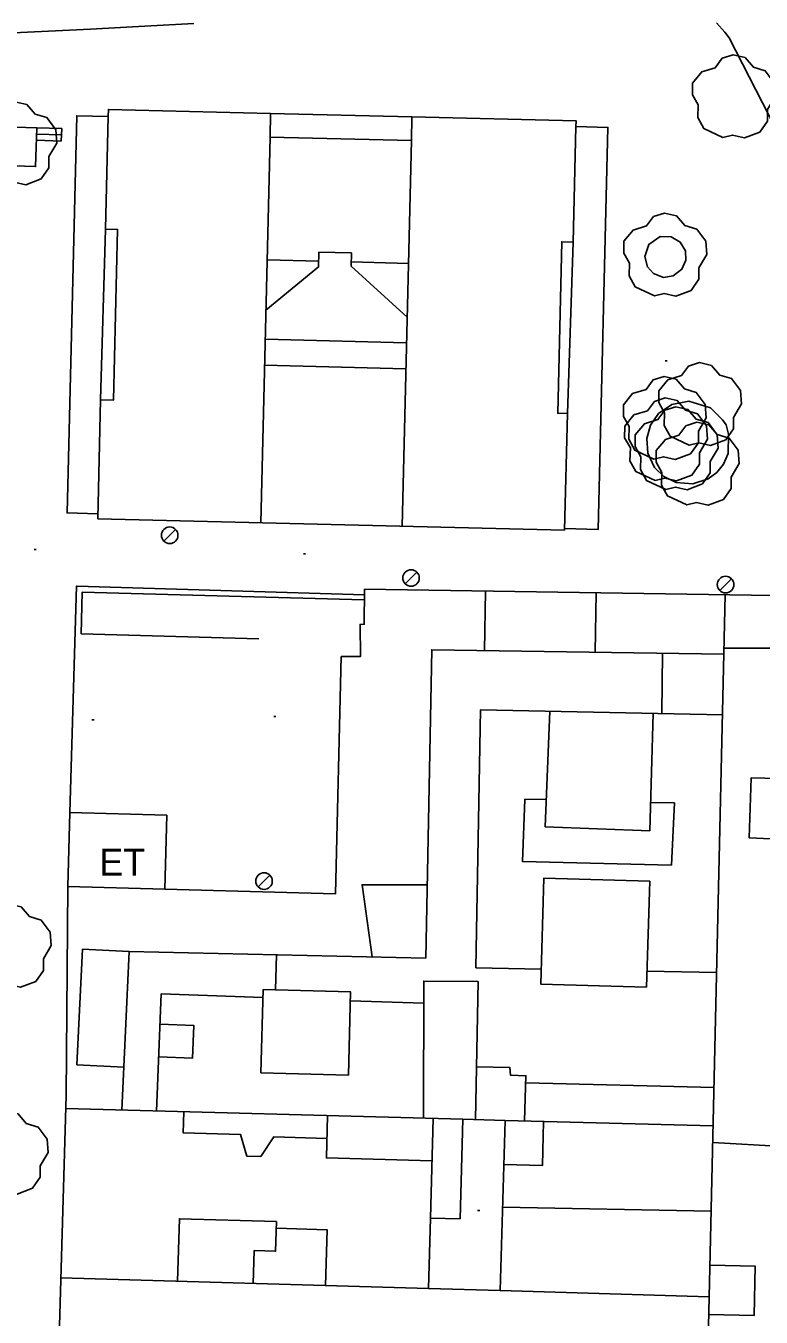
# Model space of a CAD drawing. Extents: x 431390 to 432653, y 4586754 to 4589600.
# Drawn here: x 431486.3 to 431521.7, y 4587036.9 to 4587099.1 of the extents above; entities that cross this region are included whole.
import ezdxf

# ---------------------------------------------------------------- set-up
doc = ezdxf.new("R2010")
doc.units = 0
for name, color, linetype in [('COM_17LS_LN', 7, 'Continuous'), ('CON_01_LN', 7, 'Continuous'), ('CON_01FI_LN', 7, 'Continuous'), ('CON_03_LN', 7, 'Continuous'), ('CON_04_LN', 7, 'Continuous'), ('CON_08_LN', 7, 'Continuous'), ('CON_14LS_LN', 7, 'Continuous'), ('CON_15_LN', 7, 'Continuous'), ('CON_16_LN', 7, 'Continuous'), ('CON_20_LN', 7, 'Continuous'), ('CON_23_LN', 7, 'Continuous'), ('ENE_06_PT', 7, 'Continuous'), ('ORO_03_PT', 7, 'Continuous'), ('TOP_14_TX', 7, 'Continuous'), ('VEG_03_PT', 7, 'Continuous')]:
    doc.layers.add(name, color=color, linetype=linetype)

msp = doc.modelspace()

# ---------------------------------------------------------------- linework, layer by layer
at = {"layer": 'COM_17LS_LN'}
for points in [[(431454.052, 4587099.254), (431458.563, 4587098.932), (431463.027, 4587098.704), (431467.449, 4587098.555), (431471.887, 4587098.473), (431476.364, 4587098.469), (431480.875, 4587098.554), (431485.348, 4587098.739), (431487.372, 4587098.835), (431489.397, 4587098.931), (431491.42, 4587099.04), (431494.389, 4587099.203)], [(431519.591, 4587099.231), (431519.988, 4587098.79), (431520.198, 4587098.522), (431524.709, 4587089.743), (431525.226, 4587088.745)]]:
    msp.add_lwpolyline(points, dxfattribs=at)
at = {"layer": 'CON_01_LN'}
for points in [[(431498.088, 4587094.874), (431490.265, 4587095.063), (431490.257, 4587094.724)], [(431512.813, 4587094.233), (431512.82, 4587094.517), (431504.902, 4587094.709)], [(431488.313, 4587057.601), (431488.231, 4587047.535)], [(431486.921, 4587002.7), (431487.096, 4587008.671), (431487.106, 4587009.016), (431487.323, 4587016.451), (431488.231, 4587047.535)]]:
    msp.add_lwpolyline(points, dxfattribs=at)
at = {"layer": 'CON_01FI_LN'}
for points in [[(431490.257, 4587094.724), (431490.126, 4587089.296)], [(431498.06, 4587093.724), (431498.088, 4587094.874)], [(431504.902, 4587094.709), (431504.874, 4587093.559)], [(431512.679, 4587088.669), (431512.813, 4587094.233)], [(431504.874, 4587093.559), (431498.06, 4587093.724)], [(431490.126, 4587089.296), (431489.887, 4587081.058)], [(431512.679, 4587088.669), (431512.398, 4587080.406)], [(431489.887, 4587081.058), (431489.749, 4587075.335)], [(431512.262, 4587074.789), (431512.398, 4587080.406)], [(431489.749, 4587075.334), (431512.262, 4587074.789)], [(431502.608, 4587071.939), (431502.6, 4587070.25), (431502.4, 4587070.24), (431502.42, 4587068.69), (431501.49, 4587068.69), (431501.22, 4587057.26), (431492.983, 4587057.477)], [(431502.608, 4587071.939), (431522.313, 4587071.636)], [(431488.406, 4587061.169), (431488.313, 4587057.601)], [(431492.983, 4587057.477), (431493.076, 4587061.047), (431488.406, 4587061.169)], [(431509.163, 4587038.133), (431505.703, 4587038.234), (431505.794, 4587041.629), (431507.223, 4587041.591), (431507.352, 4587046.392)], [(431507.352, 4587046.392), (431509.403, 4587046.338)], [(431509.403, 4587046.338), (431509.163, 4587038.133)]]:
    msp.add_lwpolyline(points, dxfattribs=at)
at = {"layer": 'CON_03_LN'}
for points in [[(431518.933, 4587021.903), (431518.973, 4587025.83), (431520.009, 4587071.671)], [(431492.983, 4587057.477), (431488.313, 4587057.601)], [(431488.213, 4587046.905), (431507.352, 4587046.392)], [(431509.403, 4587046.338), (431519.43, 4587046.069)], [(431487.974, 4587038.752), (431505.703, 4587038.234)], [(431509.163, 4587038.133), (431519.244, 4587037.838)]]:
    msp.add_lwpolyline(points, dxfattribs=at)
at = {"layer": 'CON_04_LN'}
for points in [[(431497.61, 4587075.144), (431498.06, 4587093.724)], [(431504.874, 4587093.559), (431504.424, 4587074.979)], [(431490.126, 4587089.296), (431490.703, 4587089.282), (431490.504, 4587081.043), (431489.887, 4587081.058)], [(431512.398, 4587080.406), (431511.932, 4587080.417), (431512.132, 4587088.682), (431512.679, 4587088.669)], [(431497.858, 4587085.389), (431500.401, 4587087.47), (431500.418, 4587088.188), (431501.987, 4587088.15), (431501.972, 4587087.509), (431504.668, 4587085.043)], [(431500.408, 4587087.748), (431497.917, 4587087.808)], [(431504.731, 4587087.643), (431501.977, 4587087.71)], [(431504.638, 4587083.817), (431497.824, 4587083.982)], [(431504.608, 4587082.564), (431497.794, 4587082.729)], [(431508.407, 4587068.981), (431508.451, 4587071.849)], [(431513.782, 4587071.767), (431513.738, 4587068.9)], [(431490.904, 4587046.833), (431491.26, 4587054.48), (431505.57, 4587054.16), (431505.86, 4587069.02), (431519.944, 4587068.805)], [(431547.7, 4587024.987), (431548.13, 4587035.11), (431527.57, 4587069.09), (431519.951, 4587069.092)], [(431516.958, 4587065.942), (431516.99, 4587068.85)], [(431519.878, 4587065.879), (431508.21, 4587066.13), (431507.99, 4587053.69), (431511.141, 4587053.63)], [(431516.541, 4587065.951), (431516.37, 4587060.3), (431511.33, 4587060.48), (431511.555, 4587066.058)], [(431523.93, 4587058.46), (431528.17, 4587058.26), (431528.31, 4587061.41), (431527.12, 4587061.42), (431527.13, 4587062.7), (431521.26, 4587062.84), (431521.17, 4587059.95), (431523.95, 4587059.83), (431523.93, 4587058.46)], [(431516.411, 4587061.66), (431517.56, 4587061.64), (431517.42, 4587058.64), (431510.23, 4587058.82), (431510.34, 4587061.81), (431511.384, 4587061.817)], [(431516.217, 4587052.751), (431516.37, 4587057.86), (431511.271, 4587058.012), (431511.119, 4587052.903), (431516.217, 4587052.751)], [(431505.639, 4587057.686), (431502.5, 4587057.69), (431502.987, 4587054.218)], [(431491, 4587048.901), (431488.747, 4587049.006), (431489.007, 4587054.585), (431491.26, 4587054.48)], [(431498.326, 4587052.628), (431498.371, 4587054.321)], [(431516.24, 4587053.533), (431519.598, 4587053.469)], [(431507.971, 4587046.376), (431508.09, 4587053.03), (431505.47, 4587053.05), (431505.457, 4587046.443)], [(431497.711, 4587052.256), (431492.81, 4587052.43), (431492.589, 4587046.788)], [(431501.84, 4587048.516), (431501.947, 4587052.531), (431497.721, 4587052.644), (431497.613, 4587048.629), (431501.84, 4587048.516)], [(431505.468, 4587051.98), (431501.936, 4587052.106)], [(431492.692, 4587049.406), (431494.32, 4587049.342), (431494.381, 4587050.911), (431492.753, 4587050.975)], [(431510.324, 4587046.313), (431510.4, 4587048.49), (431509.65, 4587048.52), (431509.63, 4587048.88), (431508.016, 4587048.911)], [(431519.472, 4587047.927), (431510.388, 4587048.14)], [(431493.901, 4587046.753), (431493.874, 4587045.729), (431496.634, 4587045.655), (431496.938, 4587044.618), (431497.611, 4587044.6), (431498.24, 4587045.538), (431500.805, 4587045.469)], [(431500.835, 4587046.567), (431500.78, 4587044.53), (431505.868, 4587044.394)], [(431505.923, 4587046.43), (431505.794, 4587041.629)], [(431511.25, 4587046.288), (431511.193, 4587044.155), (431509.341, 4587044.204)], [(431529.732, 4587019.557), (431529.93, 4587027.07), (431527.73, 4587027.05), (431528.01, 4587032.73), (431526.54, 4587032.61), (431526.05, 4587036.78), (431523.42, 4587036.76), (431523.55, 4587041.44), (431522.67, 4587041.42), (431522.77, 4587045.08), (431519.412, 4587045.274)], [(431519.337, 4587041.957), (431509.281, 4587042.158)], [(431493.597, 4587038.588), (431493.685, 4587041.595), (431498.366, 4587041.458), (431498.324, 4587040.03), (431497.292, 4587040.06), (431497.246, 4587038.481)], [(431500.732, 4587038.379), (431500.811, 4587041.066), (431498.357, 4587041.138)], [(431519.225, 4587036.98), (431521.401, 4587036.931), (431521.455, 4587039.314), (431519.279, 4587039.363)]]:
    msp.add_lwpolyline(points, dxfattribs=at)
at = {"layer": 'CON_08_LN'}
for points in [[(431490.257, 4587094.724), (431488.735, 4587094.76), (431488.267, 4587075.612), (431489.755, 4587075.575)], [(431504.902, 4587094.709), (431498.088, 4587094.874)], [(431512.813, 4587094.233), (431514.355, 4587094.197), (431513.89, 4587074.824), (431512.264, 4587074.864)]]:
    msp.add_lwpolyline(points, dxfattribs=at)
at = {"layer": 'CON_14LS_LN'}
for points in [[(431481.993, 4587094.326), (431486.811, 4587094.175), (431486.752, 4587092.305), (431481.934, 4587092.457), (431481.993, 4587094.326)], [(431502.606, 4587071.42), (431489.003, 4587071.803), (431488.946, 4587069.795), (431497.519, 4587069.553)]]:
    msp.add_lwpolyline(points, dxfattribs=at)
at = {"layer": 'CON_15_LN'}
for points in [[(431488.01, 4587094.138), (431487.991, 4587093.538)], [(431516.132, 4587087.971), (431516.322, 4587088.554), (431516.873, 4587088.931), (431517.407, 4587088.926), (431517.844, 4587088.666), (431518.09, 4587088.246), (431518.116, 4587087.799), (431517.927, 4587087.36), (431517.508, 4587087.039), (431517.029, 4587086.97), (431516.55, 4587087.151), (431516.258, 4587087.476), (431516.132, 4587087.971)], [(431518.26, 4587081.009), (431517.436, 4587080.842), (431516.788, 4587080.4), (431516.406, 4587079.85), (431516.227, 4587079.206), (431516.28, 4587078.497), (431516.608, 4587077.81), (431517.055, 4587077.372), (431517.648, 4587077.082), (431518.449, 4587077.014), (431519.186, 4587077.251), (431519.614, 4587077.57), (431519.926, 4587077.963), (431520.148, 4587078.484), (431520.175, 4587079.405), (431520.06, 4587079.868), (431519.881, 4587080.108), (431519.306, 4587080.677), (431518.26, 4587081.009)]]:
    msp.add_lwpolyline(points, dxfattribs=at)
at = {"layer": 'CON_16_LN'}
msp.add_lwpolyline([(431488.406, 4587061.169), (431488.73, 4587072.09), (431488.75, 4587072.09)], dxfattribs=at)
at = {"layer": 'CON_20_LN'}
msp.add_lwpolyline([(431488.75, 4587072.09), (431502.607, 4587071.67)], dxfattribs=at)
at = {"layer": 'CON_23_LN'}
for points in [[(431486.811, 4587094.175), (431488.01, 4587094.138)], [(431486.792, 4587093.575), (431487.991, 4587093.538)], [(431486.802, 4587093.875), (431488, 4587093.838)]]:
    msp.add_lwpolyline(points, dxfattribs=at)
at = {"layer": 'ENE_06_PT'}
for p, q in [((431493.502, 4587074.822), (431492.936, 4587074.256)), ((431505.142, 4587072.762), (431504.576, 4587072.196)), ((431520.312, 4587072.444), (431519.746, 4587071.878)), ((431498.052, 4587058.152), (431497.486, 4587057.586))]:
    msp.add_line(p, q, dxfattribs=at)
for centre in [(431493.219, 4587074.539), (431504.859, 4587072.479), (431520.029, 4587072.161), (431497.769, 4587057.869)]:
    msp.add_circle(centre, 0.4, dxfattribs=at)
at = {"layer": 'ORO_03_PT'}
for p, q in [((431517.12, 4587082.95), (431517.22, 4587082.95)), ((431486.68, 4587073.85), (431486.78, 4587073.85)), ((431499.67, 4587073.64), (431499.77, 4587073.64)), ((431489.47, 4587065.64), (431489.57, 4587065.64)), ((431498.24, 4587065.81), (431498.34, 4587065.81)), ((431508.07, 4587041.99), (431508.17, 4587041.99))]:
    msp.add_line(p, q, dxfattribs=at)
at = {"layer": 'VEG_03_PT'}
for points in [[(431519.904, 4587093.711), (431518.977, 4587094.146), (431518.689, 4587094.667), (431518.712, 4587095.281), (431518.43, 4587095.773), (431518.438, 4587096.336), (431518.879, 4587096.871), (431519.532, 4587097.075), (431519.867, 4587097.526), (431520.393, 4587097.696), (431520.973, 4587097.563), (431521.373, 4587097.097), (431521.947, 4587096.927), (431522.381, 4587096.344), (431522.43, 4587095.702), (431522.047, 4587095.055), (431522.047, 4587094.505), (431521.675, 4587093.971), (431520.936, 4587093.696), (431520.371, 4587093.824), (431519.904, 4587093.711)], [(431485.254, 4587091.451), (431484.327, 4587091.886), (431484.039, 4587092.407), (431484.062, 4587093.021), (431483.78, 4587093.513), (431483.788, 4587094.076), (431484.229, 4587094.611), (431484.882, 4587094.815), (431485.217, 4587095.266), (431485.743, 4587095.436), (431486.323, 4587095.303), (431486.723, 4587094.837), (431487.297, 4587094.667), (431487.731, 4587094.084), (431487.78, 4587093.442), (431487.397, 4587092.795), (431487.397, 4587092.245), (431487.025, 4587091.711), (431486.286, 4587091.436), (431485.721, 4587091.564), (431485.254, 4587091.451)], [(431516.594, 4587086.081), (431515.667, 4587086.516), (431515.379, 4587087.037), (431515.402, 4587087.651), (431515.12, 4587088.143), (431515.128, 4587088.706), (431515.569, 4587089.241), (431516.222, 4587089.445), (431516.557, 4587089.896), (431517.083, 4587090.066), (431517.663, 4587089.933), (431518.063, 4587089.467), (431518.637, 4587089.297), (431519.071, 4587088.714), (431519.12, 4587088.072), (431518.737, 4587087.425), (431518.737, 4587086.875), (431518.365, 4587086.341), (431517.626, 4587086.066), (431517.061, 4587086.194), (431516.594, 4587086.081)], [(431518.277, 4587078.875), (431517.35, 4587079.31), (431517.062, 4587079.831), (431517.085, 4587080.445), (431516.803, 4587080.937), (431516.811, 4587081.5), (431517.252, 4587082.035), (431517.905, 4587082.239), (431518.24, 4587082.69), (431518.766, 4587082.86), (431519.346, 4587082.727), (431519.746, 4587082.261), (431520.32, 4587082.091), (431520.754, 4587081.508), (431520.803, 4587080.866), (431520.42, 4587080.219), (431520.42, 4587079.669), (431520.048, 4587079.135), (431519.309, 4587078.86), (431518.744, 4587078.988), (431518.277, 4587078.875)], [(431516.573, 4587078.207), (431515.646, 4587078.642), (431515.358, 4587079.163), (431515.381, 4587079.777), (431515.099, 4587080.269), (431515.107, 4587080.832), (431515.548, 4587081.367), (431516.201, 4587081.571), (431516.536, 4587082.022), (431517.062, 4587082.192), (431517.642, 4587082.059), (431518.042, 4587081.593), (431518.616, 4587081.423), (431519.05, 4587080.84), (431519.099, 4587080.198), (431518.716, 4587079.551), (431518.716, 4587079.001), (431518.344, 4587078.467), (431517.605, 4587078.192), (431517.04, 4587078.32), (431516.573, 4587078.207)], [(431516.634, 4587077.175), (431515.707, 4587077.61), (431515.419, 4587078.131), (431515.442, 4587078.745), (431515.16, 4587079.237), (431515.168, 4587079.8), (431515.609, 4587080.335), (431516.262, 4587080.539), (431516.597, 4587080.99), (431517.123, 4587081.16), (431517.703, 4587081.027), (431518.103, 4587080.561), (431518.677, 4587080.391), (431519.111, 4587079.808), (431519.16, 4587079.166), (431518.777, 4587078.519), (431518.777, 4587077.969), (431518.405, 4587077.435), (431517.666, 4587077.16), (431517.101, 4587077.288), (431516.634, 4587077.175)], [(431517.141, 4587076.75), (431516.214, 4587077.185), (431515.926, 4587077.706), (431515.949, 4587078.32), (431515.667, 4587078.812), (431515.675, 4587079.375), (431516.116, 4587079.91), (431516.769, 4587080.114), (431517.104, 4587080.565), (431517.63, 4587080.735), (431518.21, 4587080.602), (431518.61, 4587080.136), (431519.184, 4587079.966), (431519.618, 4587079.383), (431519.667, 4587078.741), (431519.284, 4587078.094), (431519.284, 4587077.544), (431518.912, 4587077.01), (431518.173, 4587076.735), (431517.608, 4587076.863), (431517.141, 4587076.75)], [(431518.155, 4587076.001), (431517.228, 4587076.436), (431516.94, 4587076.957), (431516.963, 4587077.571), (431516.681, 4587078.063), (431516.689, 4587078.626), (431517.13, 4587079.161), (431517.783, 4587079.365), (431518.118, 4587079.816), (431518.644, 4587079.986), (431519.224, 4587079.853), (431519.624, 4587079.387), (431520.198, 4587079.217), (431520.632, 4587078.634), (431520.681, 4587077.992), (431520.298, 4587077.345), (431520.298, 4587076.795), (431519.926, 4587076.261), (431519.187, 4587075.986), (431518.622, 4587076.114), (431518.155, 4587076.001)], [(431484.984, 4587052.771), (431484.057, 4587053.206), (431483.769, 4587053.727), (431483.792, 4587054.341), (431483.51, 4587054.833), (431483.518, 4587055.396), (431483.959, 4587055.931), (431484.612, 4587056.135), (431484.947, 4587056.586), (431485.473, 4587056.756), (431486.053, 4587056.623), (431486.453, 4587056.157), (431487.027, 4587055.987), (431487.461, 4587055.404), (431487.51, 4587054.762), (431487.127, 4587054.115), (431487.127, 4587053.565), (431486.755, 4587053.031), (431486.016, 4587052.756), (431485.451, 4587052.884), (431484.984, 4587052.771)], [(431484.834, 4587042.801), (431483.907, 4587043.236), (431483.619, 4587043.757), (431483.642, 4587044.371), (431483.36, 4587044.863), (431483.368, 4587045.426), (431483.809, 4587045.961), (431484.462, 4587046.165), (431484.797, 4587046.616), (431485.323, 4587046.786), (431485.903, 4587046.653), (431486.303, 4587046.187), (431486.877, 4587046.017), (431487.311, 4587045.434), (431487.36, 4587044.792), (431486.977, 4587044.145), (431486.977, 4587043.595), (431486.605, 4587043.061), (431485.866, 4587042.786), (431485.301, 4587042.914), (431484.834, 4587042.801)]]:
    msp.add_lwpolyline(points, dxfattribs=at)

# ---------------------------------------------------------------- texts
at = {"layer": 'TOP_14_TX'}
msp.add_text('ET', height=1.3, dxfattribs=at).set_placement((431489.822, 4587058.137))

doc.saveas('drawing.dxf')
